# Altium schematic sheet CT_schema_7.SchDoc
size 277 x 170 mm
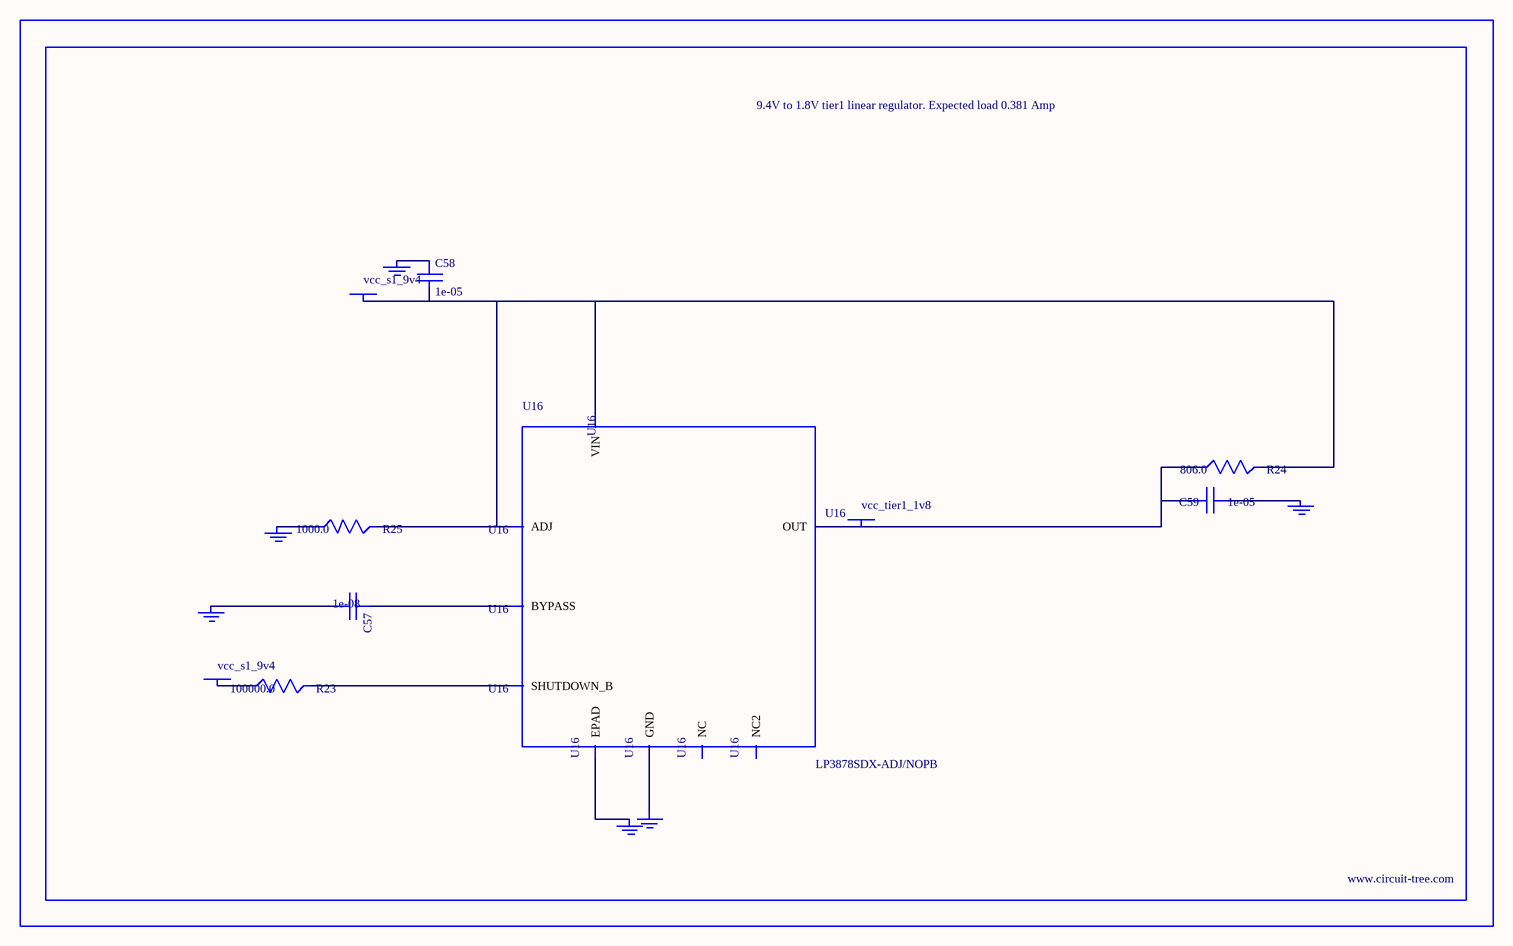
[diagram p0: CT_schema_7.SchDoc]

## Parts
BORDER6  (no value)
C57  1e-08  [C0402]
C58  1e-05  [C1206]
C59  1e-05  [C0805]
GND_INSTANCE_6_0  (no value)
GND_INSTANCE_6_1  (no value)
GND_INSTANCE_6_2  (no value)
GND_INSTANCE_6_3  (no value)
GND_INSTANCE_6_4  (no value)
GND_INSTANCE_6_5  (no value)
POWER_INSTANCE_6_0  vcc_s1_9v4
POWER_INSTANCE_6_1  vcc_s1_9v4
POWER_INSTANCE_6_2  vcc_tier1_1v8
R23  100000.0  [R0603]
R24  806.0  [R0603]
R25  1000.0  [R0603]
U16  LP3878SDX-ADJ/NOPB  [WSON-8]

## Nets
NetC57_1: C57.1 U16.1(BYPASS)
NetC57_2: C57.2 GND_INSTANCE_6_0.0(GND)
NetC58_1: C58.1 GND_INSTANCE_6_1.0(GND)
NetC58_2: C58.2 POWER_INSTANCE_6_0.0(PWR) R24.2 R25.2 U16.4(VIN) U16.6(ADJ)
NetC59_1: C59.1 GND_INSTANCE_6_2.0(GND)
NetC59_2: C59.2 POWER_INSTANCE_6_2.0(PWR) R24.1 U16.5(OUT)
NetGND_INSTANCE_6_3_0: GND_INSTANCE_6_3.0(GND) R25.1
NetGND_INSTANCE_6_4_0: GND_INSTANCE_6_4.0(GND) U16.PAD(EPAD)
NetGND_INSTANCE_6_5_0: GND_INSTANCE_6_5.0(GND) U16.3(GND)
NetPOWER_INSTANCE_6_1_0: POWER_INSTANCE_6_1.0(PWR) R23.1
NetR23_2: R23.2 U16.8(SHUTDOWN_B)

Not connected (* = marked no-connect by the designer): U16 2(NC) 7(NC2)

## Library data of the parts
BORDER6 = BORDER_PAGE6
C57 = C0402C103K3RAC
C58 = C1206C106K3RACTU
C59 = GRM219R60J106ME19D
GND_INSTANCE_6_0-GND_INSTANCE_6_5 = GND
POWER_INSTANCE_6_0-POWER_INSTANCE_6_2 = PWR
R23 = RC0603JR-07100KL
R24 = ERJ-3EKF8060V
R25 = RC0603JR-071KL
